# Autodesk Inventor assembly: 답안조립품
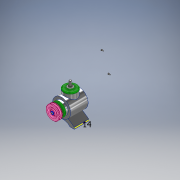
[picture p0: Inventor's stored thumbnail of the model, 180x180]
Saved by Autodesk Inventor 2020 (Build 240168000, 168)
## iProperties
Created: 2023-12
Part Number: 답안조립품
Document SubType Name: Assembly
Designer: 1강의실14
Author: 1강의실14
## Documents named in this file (17)
- C:\Users\1강의실14\Desktop\731203V1007\답안조립품.iam
- C:\Users\1강의실14\Desktop\731203V1007\본체.ipt
- C:\Users\1강의실14\Desktop\731203V1007\V-벨트풀리.ipt
- C:\Users\1강의실14\Desktop\731203V1007\메인 베벨기어.ipt
- C:\Users\1강의실14\Desktop\731203V1007\메인 축.ipt
- 메인 축.ipt
- C:\Users\1강의실14\Desktop\731203V1007\베어링 6203.ipt
- C:\Users\1강의실14\Desktop\731203V1007\볼트 M4 x 10.ipt
- C:\Users\1강의실14\Desktop\731203V1007\서브 베벨기어.ipt
- C:\Users\1강의실14\Desktop\731203V1007\서브 축.ipt
- 서브 축.ipt
- C:\Users\1강의실14\Desktop\731203V1007\오일실 17 x 32 x 8.ipt
- C:\Users\1강의실14\Desktop\731203V1007\와셔 4 x 16.ipt
- C:\Users\1강의실14\Desktop\731203V1007\육각볼트 M4 x 8.ipt
- C:\Users\1강의실14\Desktop\731203V1007\커버.ipt
- C:\Users\1강의실14\Desktop\731203V1007\키 4 x 4 x 14.ipt
- C:\Users\1강의실14\Desktop\731203V1007\키 5 x 5 x 14.ipt
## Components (1 placed, 1 different names)
1. V-벨트풀리:1 — 각도:3
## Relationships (1: Angle 1)
- 각도:3 [Angle]: V-벨트풀리:1
